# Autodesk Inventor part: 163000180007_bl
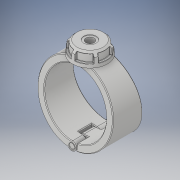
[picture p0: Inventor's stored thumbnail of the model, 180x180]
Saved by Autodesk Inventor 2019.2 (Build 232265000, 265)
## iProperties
Created: 2022-02
Part Number: 163000180007_bl
Material: Generic
Description: Plassadle Threaded 180x3/4''
Document SubType Name: Modeling
Designer: comp2
Density: 1 g/cm^3
Appearance: Default
Author: comp2
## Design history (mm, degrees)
derived "16300.ipt"
feature "Solid1::16300.ipt" dims "ScaleForDerivedMember" = 10
feature "Solid2::16300.ipt" dims "ScaleForDerivedMember" = 10
feature "Solid3::16300.ipt" dims "ScaleForDerivedMember" = 10
feature "Solid4::16300.ipt" dims "ScaleForDerivedMember" = 10
tag "TaggingFeature1"
body "Solid1"
body "Solid2"
body "Solid3"
body "Solid4"
other parameters: "d7" = 209 [user parameter], "d8" = 85 deg [user parameter], "d9" = 45 deg [user parameter], "d10" = 102 [user parameter], "d11" = 49 [user parameter], "d12" = 25.27 [user parameter], "d13" = 42.84 [user parameter], "d14" = 36.1755 [user parameter], "d42" = 4 [user parameter], "d49" = 4.4 [user parameter], "d51" = 0 [user parameter], "d52" = 28 [user parameter], "d53" = 121 [user parameter], "d54" = 38.5 [user parameter], "d55" = 0 [user parameter], "d56" = 22 [user parameter], "d57" = 22 [user parameter], "d59" = 0 [user parameter], "d61" = 0 [user parameter], "d62" = 38.5 [user parameter], "d63" = 0 [user parameter], "d65" = 0 [user parameter], "d67" = 0 [user parameter], "d69" = 0 [user parameter], "d70" = 1 [user parameter], "d71" = 105.6 [user parameter], "d72" = 0 [user parameter], "d73" = 2 [user parameter], "d78" = 86.7 [user parameter], "d79" = 5.1 [user parameter], "d80" = 60 deg [user parameter], "d81" = 5.1 [user parameter], "d84" = 0 [user parameter], "d85" = 1 [user parameter], "d87" = 360 deg [user parameter], "d122" = 49 [user parameter], "d124" = 42.80128 [user parameter], "d125" = 1.805 [user parameter], "d127" = 255 [user parameter], "d129" = 24.117 [user parameter], "d130" = 20.49945 [user parameter], "d131" = 31.85 [user parameter], "d132" = 45 deg [user parameter], "d133" = 22.295 [user parameter], "d134" = 12.0585 [user parameter], "d136" = 0 [user parameter], "d138" = 0 [user parameter], "d1" = 25 [user parameter], "E_" = 54 [user parameter], "E1" = 102 [user parameter], "H1" = 255 [user parameter], "H2" = 49 [user parameter], "H3" = 78 [user parameter], "H_costum" = 49 [user parameter], "Rp" = 24.117 [user parameter], "d128" = 36.1 [user parameter]
